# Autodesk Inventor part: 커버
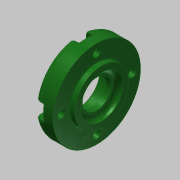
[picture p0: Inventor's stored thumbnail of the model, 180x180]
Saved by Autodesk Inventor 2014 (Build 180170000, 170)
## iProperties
Created: 2015-11
Part Number: 커버
Material: 알루미늄 6061
Document SubType Name: Modeling
Designer: mduedu
Density: 1 g/cm^3
Appearance: Smooth - Dark Forest Green
Author: mduedu
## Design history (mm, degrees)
sketch "스케치1"
  geometry: L1 (-7, 0)-(7, 0); L2 (-7, 0)-(-7, 26); L3 (-7, 26)-(4, 26); L4 (4, 26)-(4, 16); L5 (4, 16)-(7, 16); L6 (7, 16)-(7, 0); 2 further points
  constraints: 12 end point, 3 perpendicular, 2 parallel, 1 coincident, 1 horizontal, 1 midpoint
  dimensions: "d0" = 14 distance of L1.start L1.end; "d1" = 52 diameter of L3 L1; "d2" = 3 distance of L4.end L5.end; "d3" = 32 diameter of L5 L1
revolve "회전1" sketch "스케치1" stored, may be unused: angle "d4" = 90 deg
hole "구멍1" diameter "d7" = 25; stored, may be unused: countersink angle "d11" = 90 deg, drill point angle "d13" = 0 deg; dims "d5" = 10, "d6" = 10, "d8" = 6, "d9" = 4, "d10" = 2, "d12" = 3
hole "구멍2" diameter "d16" = 25; stored, may be unused: countersink angle "d20" = 90 deg, drill point angle "d22" = 0 deg; dims "d17" = 6, "d18" = 4, "d19" = 2, "d21" = 7.7, "d58" = 10, "d59" = 10
hole "구멍3" diameter "d25" = 17; stored, may be unused: countersink angle "d29" = 90 deg, drill point angle "d31" = 0 deg; dims "d23" = 10, "d24" = 10, "d26" = 6, "d27" = 4, "d28" = 2, "d30" = 4.2
chamfer "모따기1" distance "d32" = 0.6; stored, may be unused: second distance "d33" = 2, angle "d34" = 30 deg
fillet "모깎기1" dims "d35" = 0.3
fillet "모깎기2" dims "d36" = 3
fillet "모깎기3" dims "d37" = 3
fillet "모깎기4" dims "d38" = 0.3
sketch "스케치3" dims "d61" = 42
  geometry: C1 r 26 at (0, 0) reference; 2 further points
  constraints: 2 vertical alignment, 1 coincident, 2 other
hole "구멍4" sketch "스케치3" at (0, -21) diameter "d44" = 4.5; stored, may be unused: countersink angle "d48" = 90 deg, drill point angle "d50" = 0 deg; dims "d45" = 6, "d46" = 8, "d47" = 4.6, "d49" = 8
sketch "스케치4"
  geometry: L1 (-4, 0)-(-4, -4.69); L2 (4, 0)-(4, -4.69); A1 r 4 centre (0, 0) between (3.614, -1.714) and (-3.614, -1.714) reference; A2 r 26 centre (0, 21) between (-4, -4.69) and (4, -4.69) reference; 1 further point
  constraints: 4 end point, 4 point on circle, 2 tangent, 1 parallel, 1 vertical
extrude "돌출1" cut sketch "스케치4" stored distance "d51" = 0; taper "d52" = 0 deg
fillet "모깎기5" dims "d56" = 0.3
fillet "모깎기6" dims "d57" = 1
node "솔리드1"
pattern_circular "원형 패턴1" dims angle "d54" = 360 deg
